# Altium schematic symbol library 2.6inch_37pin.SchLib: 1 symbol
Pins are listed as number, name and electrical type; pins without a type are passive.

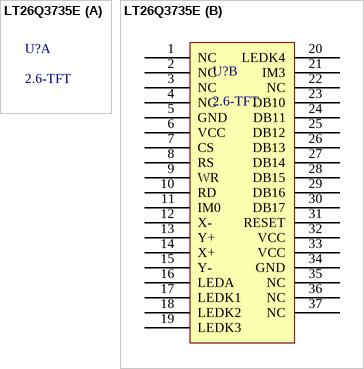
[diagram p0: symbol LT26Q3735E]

## LT26Q3735E
designator U?, comment 2.6-TFT
2.6inch TFT LCD
part B pins: 1 NC, 2 NC, 3 NC, 4 NC, 5 GND, 6 VCC, 7 CS, 8 RS, 9 WR, 10 RD, 11 IM0, 12 X-, 13 Y+, 14 X+, 15 Y-, 16 LEDA, 17 LEDK1, 18 LEDK2, 19 LEDK3, 20 LEDK4, 21 IM3, 22 NC, 23 DB10, 24 DB11, 25 DB12, 26 DB13, 27 DB14, 28 DB15, 29 DB16, 30 DB17, 31 RESET, 32 VCC, 33 VCC, 34 GND, 35 NC, 36 NC, 37 NC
